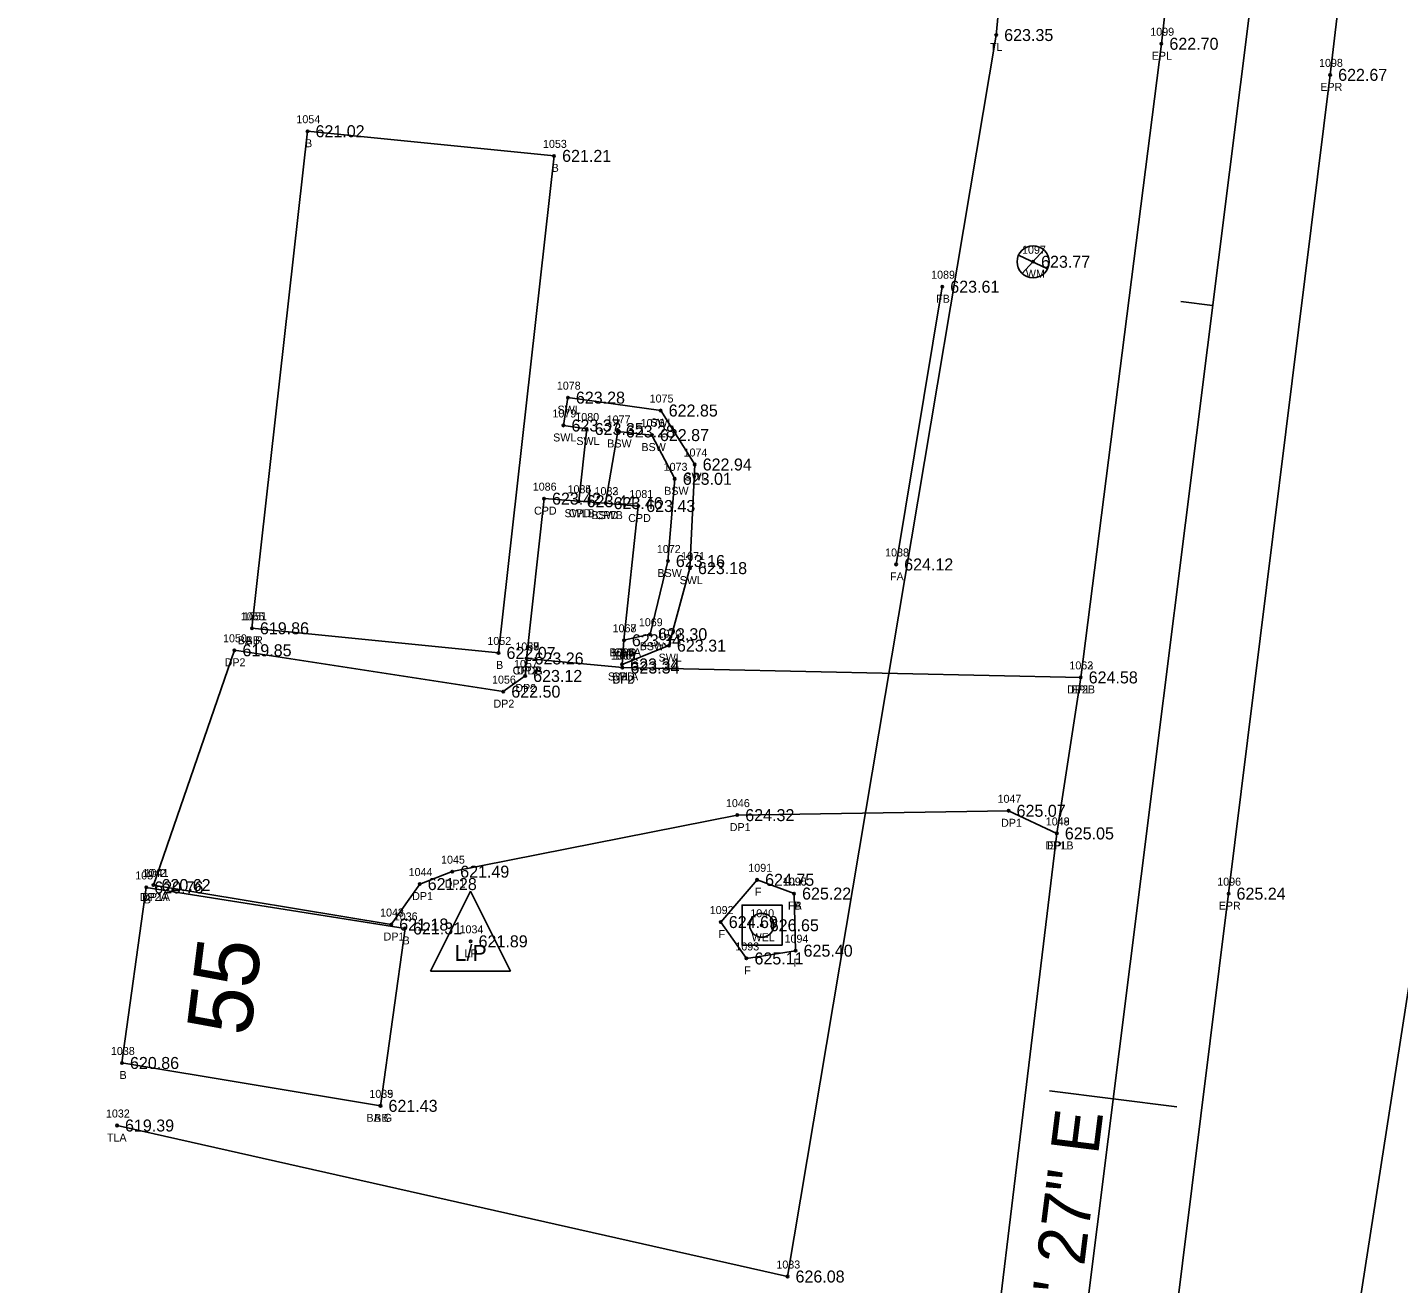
# Model space of a CAD drawing. Extents: x 1694813 to 1696862, y 1086485 to 1091027.
# Drawn here: x 1695755.8 to 1695927.2, y 1087718.4 to 1087875.5 of the extents above; entities that cross this region are included whole.
import ezdxf

# ---------------------------------------------------------------- set-up
doc = ezdxf.new("R2010")
doc.units = 0
for name, color, linetype in [('RD_EX_Bldg', 7, 'Continuous'), ('RD_EX_Bldg_txCode', 7, 'Continuous'), ('RD_EX_BldgApp_txCode', 7, 'Continuous'), ('RD_EX_Conc', 7, 'Continuous'), ('RD_EX_Conc_txCode', 7, 'Continuous'), ('RD_EX_Driveway', 7, 'Continuous'), ('RD_EX_Driveway_txCode', 7, 'Continuous'), ('RD_EX_Fence_Other', 7, 'Continuous'), ('RD_EX_Road', 7, 'Continuous'), ('RD_EX_Road_txCode', 7, 'Continuous'), ('RD_EX_SU_H2O', 7, 'Continuous'), ('RD_EX_TX_Bldg_ELEV', 7, 'Continuous'), ('RD_EX_TX_BldgApp_ELEV', 7, 'Continuous'), ('RD_EX_TX_Conc_ELEV', 7, 'Continuous'), ('RD_EX_TX_Driveway_ELEV', 7, 'Continuous'), ('RD_EX_TX_Road_ELEV', 7, 'Continuous'), ('RD_EX_TX_UT_ELEV', 7, 'Continuous'), ('RD_EX_TX_VEG_ELEV', 7, 'Continuous'), ('RD_EX_UT', 7, 'Continuous'), ('RD_EX_UT_txCode', 7, 'Continuous'), ('RD_EX_VEG', 7, 'Continuous'), ('RD_EX_VEG_txCode', 7, 'Continuous'), ('RD_HC_Cl', 7, 'Continuous'), ('RD_HC_Data', 7, 'Continuous'), ('RD_HC_Data_Tic', 7, 'Continuous'), ('RD_HC_TX_Sta50', 7, 'Continuous'), ('RD_SMD_Locator', 7, 'Continuous')]:
    doc.layers.add(name, color=color, linetype=linetype)

msp = doc.modelspace()

# ---------------------------------------------------------------- linework, layer by layer
at = {"layer": 'RD_EX_Bldg'}
for points in [[(1695783.9, 1087800.34), (1695814.72, 1087797.26), (1695821.67, 1087859.41), (1695790.85, 1087862.49), (1695783.9, 1087800.34)], [(1695799.97, 1087740.63), (1695803.04, 1087762.81), (1695770.7, 1087767.94), (1695767.66, 1087745.99), (1695799.97, 1087740.63)]]:
    msp.add_lwpolyline(points, dxfattribs=at)
at = {"layer": 'RD_EX_BldgApp_txCode'}
msp.add_circle((1695847.62, 1087763.21), 0.15, dxfattribs=at)
at = {"layer": 'RD_EX_Conc'}
for points in [[(1695830.17, 1087795.82), (1695836.02, 1087798.17), (1695838.65, 1087807.86), (1695839.24, 1087820.82), (1695834.99, 1087827.57), (1695823.39, 1087829.18), (1695822.84, 1087825.7), (1695825.74, 1087825.26), (1695824.74, 1087816.23)], [(1695830.39, 1087798.84), (1695833.67, 1087799.6), (1695835.89, 1087808.75), (1695836.75, 1087819.03), (1695833.89, 1087824.5), (1695829.63, 1087824.95), (1695828.1, 1087815.99)], [(1695818.22, 1087796.57), (1695830.21, 1087795.43), (1695830.17, 1087795.82), (1695830.17, 1087795.82), (1695830.39, 1087798.84), (1695832.18, 1087815.63), (1695828.1, 1087815.99), (1695824.74, 1087816.23), (1695820.41, 1087816.55), (1695818.22, 1087796.57)]]:
    msp.add_lwpolyline(points, dxfattribs=at)
at = {"layer": 'RD_EX_Driveway'}
for points in [[(1695771.6, 1087768.24), (1695781.72, 1087797.59), (1695815.32, 1087792.42), (1695818.05, 1087794.38), (1695818.22, 1087796.57), (1695830.21, 1087795.43), (1695887.48, 1087794.2)], [(1695771.6, 1087768.24), (1695801.31, 1087763.3), (1695804.87, 1087768.36), (1695808.93, 1087769.91), (1695844.56, 1087776.98), (1695878.47, 1087777.52), (1695884.5, 1087774.69)]]:
    msp.add_lwpolyline(points, dxfattribs=at)
at = {"layer": 'RD_EX_Fence_Other'}
msp.add_lwpolyline([(1695896.34, 1087555.36), (1695913.97, 1087661.92), (1695929.73, 1087763.6), (1695939.84, 1087832.07), (1696009.84, 1087821.33)], dxfattribs=at)
at = {"layer": 'RD_EX_Road'}
for points in [[(1695879.87, 1087561.29), (1695893.33, 1087665.71), (1695905.96, 1087767.16), (1695918.66, 1087869.54), (1695930.87, 1087972.82), (1695936.26, 1088023.68), (1695942.14, 1088076.32), (1695948.07, 1088128.17), (1695955.04, 1088181.4), (1695962.88, 1088230.72), (1695971.68, 1088284.64), (1695982.02, 1088336.12), (1695993.28, 1088388.48), (1696018.75, 1088494.48), (1696045.23, 1088599.95), (1696055.72, 1088654.41), (1696060.15, 1088705.35), (1696055.83, 1088758.02), (1696044.01, 1088812.16), (1696026.4, 1088860.33), (1696000.41, 1088911.48), (1695972.46, 1088953.82), (1695939.48, 1088998.73), (1695931.21, 1088992.88)], [(1695858.19, 1087564.9), (1695871.71, 1087668.82), (1695884.5, 1087774.69), (1695887.48, 1087794.2), (1695897.57, 1087873.43), (1695908.92, 1087975.76), (1695914.49, 1088029.24), (1695917.65, 1088054.8), (1695920.27, 1088079.09), (1695926.98, 1088130.26), (1695934.75, 1088185.09), (1695942.15, 1088234.62), (1695951.36, 1088288.06), (1695961.48, 1088338.41), (1695972.86, 1088394.13), (1695998.53, 1088499.67), (1696024.81, 1088603.86), (1696034.83, 1088656.78)]]:
    msp.add_lwpolyline(points, dxfattribs=at)
at = {"layer": 'RD_EX_SU_H2O'}
msp.add_lwpolyline([(1695845.16, 1087760.74), (1695845.16, 1087765.74), (1695850.16, 1087765.74), (1695850.16, 1087760.74)], close=True, dxfattribs=at)
msp.add_circle((1695847.62, 1087763.21), 1.5, dxfattribs=at)
at = {"layer": 'RD_EX_UT'}
for p, q in [((1695880.18, 1087844.71), (1695882.85, 1087847.6)), ((1695879.7, 1087847), (1695883.33, 1087845.29)), ((1695806.23, 1087757.47), (1695811.23, 1087767.47)), ((1695811.23, 1087767.47), (1695816.23, 1087757.47)), ((1695806.23, 1087757.47), (1695816.23, 1087757.47))]:
    msp.add_line(p, q, dxfattribs=at)
msp.add_circle((1695881.53, 1087846.17), 2, dxfattribs=at)
at = {"layer": 'RD_EX_VEG'}
msp.add_line((1695864.42, 1087808.32), (1695870.18, 1087843.05), dxfattribs=at)
for points in [[(1695767.04, 1087738.17), (1695850.84, 1087719.29), (1695876.92, 1087874.52), (1695886.77, 1087978.73), (1695882.04, 1088123.19), (1695966.35, 1088397.22), (1695987.61, 1088500.99), (1696016.82, 1088604.01), (1696023.94, 1088658.84), (1696026.75, 1088706.17), (1696020.44, 1088756.26), (1696012.04, 1088803.02), (1695995.69, 1088847.32), (1695967.16, 1088892.48), (1695790.95, 1089107.47), (1695767.01, 1089177.35), (1695741.24, 1089223.37), (1695720.39, 1089271.33), (1695703.52, 1089329.03), (1695695, 1089381.13)], [(1695851.66, 1087767.17), (1695847.04, 1087768.89), (1695842.5, 1087763.61), (1695845.71, 1087759.06), (1695851.85, 1087760.03), (1695851.66, 1087767.17)]]:
    msp.add_lwpolyline(points, dxfattribs=at)
at = {"layer": 'RD_HC_Cl'}
msp.add_line((1695866.12, 1087538.58), (1695910.69, 1087894.29), dxfattribs=at)
at = {"layer": 'RD_HC_Data_Tic'}
for p, q in [((1695903.97, 1087840.72), (1695900, 1087841.21)), ((1695891.54, 1087741.49), (1695883.6, 1087742.49)), ((1695891.54, 1087741.49), (1695899.48, 1087740.5))]:
    msp.add_line(p, q, dxfattribs=at)
at = {"layer": 'RD_SMD_Locator'}
for centre in [(1695876.92, 1087874.52), (1695897.57, 1087873.43), (1695918.66, 1087869.54), (1695790.85, 1087862.49), (1695821.67, 1087859.41), (1695881.53, 1087846.17), (1695870.18, 1087843.05), (1695823.39, 1087829.18), (1695834.99, 1087827.57), (1695822.84, 1087825.7), (1695825.74, 1087825.26), (1695829.63, 1087824.95), (1695833.89, 1087824.5), (1695839.24, 1087820.82), (1695836.75, 1087819.03), (1695820.41, 1087816.55), (1695824.74, 1087816.23), (1695824.74, 1087816.23), (1695828.1, 1087815.99), (1695828.1, 1087815.99), (1695832.18, 1087815.63), (1695835.89, 1087808.75), (1695838.65, 1087807.86), (1695864.42, 1087808.32), (1695783.9, 1087800.34), (1695783.9, 1087800.34), (1695833.67, 1087799.6), (1695781.72, 1087797.59), (1695830.39, 1087798.84), (1695830.39, 1087798.84), (1695836.02, 1087798.17), (1695814.72, 1087797.26), (1695818.22, 1087796.57), (1695818.22, 1087796.57), (1695818.22, 1087796.57), (1695830.17, 1087795.82), (1695830.17, 1087795.82), (1695830.17, 1087795.82), (1695818.05, 1087794.38), (1695830.21, 1087795.43), (1695830.21, 1087795.43), (1695887.48, 1087794.2), (1695887.48, 1087794.2), (1695815.32, 1087792.42), (1695844.56, 1087776.98), (1695878.47, 1087777.52), (1695884.5, 1087774.69), (1695884.5, 1087774.69), (1695804.87, 1087768.36), (1695808.93, 1087769.91), (1695847.04, 1087768.89), (1695770.7, 1087767.94), (1695771.6, 1087768.24), (1695771.6, 1087768.24), (1695851.66, 1087767.17), (1695851.66, 1087767.17), (1695905.96, 1087767.16), (1695801.31, 1087763.3), (1695842.5, 1087763.61), (1695803.04, 1087762.81), (1695811.23, 1087761.2), (1695851.85, 1087760.03), (1695845.71, 1087759.06), (1695767.66, 1087745.99), (1695799.97, 1087740.63), (1695799.97, 1087740.63), (1695767.04, 1087738.17), (1695850.84, 1087719.29)]:
    msp.add_circle(centre, 0.15, dxfattribs=at)

# ---------------------------------------------------------------- texts
at = {"layer": 'RD_EX_Bldg_txCode'}
for s, p in [('1054', (1695789.46, 1087863.49)), ('B', (1695790.54, 1087860.49)), ('1053', (1695820.28, 1087860.41)), ('B', (1695821.36, 1087857.41)), ('1055', (1695782.51, 1087801.34)), ('1051', (1695782.79, 1087801.34)), ('BA R', (1695782.14, 1087798.34)), ('BB', (1695783.12, 1087798.34)), ('1052', (1695813.33, 1087798.26)), ('B', (1695814.41, 1087795.26)), ('1037', (1695769.32, 1087768.94)), ('B', (1695770.4, 1087765.94)), ('1036', (1695801.63, 1087763.81)), ('B', (1695802.73, 1087760.81)), ('1038', (1695766.28, 1087746.99)), ('B', (1695767.36, 1087743.99)), ('1035', (1695798.58, 1087741.63)), ('1039', (1695798.58, 1087741.63)), ('BA G', (1695798.21, 1087738.63)), ('BB', (1695799.19, 1087738.63))]:
    msp.add_text(s, height=1, dxfattribs=at).set_placement(p)
at = {"layer": 'RD_EX_BldgApp_txCode'}
for s, p in [('1040', (1695846.19, 1087764.21)), ('WEL', (1695846.35, 1087761.21))]:
    msp.add_text(s, height=1, dxfattribs=at).set_placement(p)
at = {"layer": 'RD_EX_Conc_txCode'}
for s, p in [('1078', (1695822.01, 1087830.18)), ('1075', (1695833.61, 1087828.57)), ('1079', (1695821.46, 1087826.7)), ('SWL', (1695822.1, 1087827.18)), ('1080', (1695824.32, 1087826.26)), ('1077', (1695828.24, 1087825.95)), ('1076', (1695832.48, 1087825.5)), ('SWL', (1695833.7, 1087825.57)), ('SWL', (1695821.55, 1087823.7)), ('SWL', (1695824.45, 1087823.26)), ('BSW', (1695828.31, 1087822.95)), ('BSW', (1695832.58, 1087822.5)), ('1074', (1695837.85, 1087821.82)), ('1073', (1695835.36, 1087820.03)), ('1086', (1695819, 1087817.55)), ('1084', (1695823.35, 1087817.23)), ('1085', (1695823.35, 1087817.23)), ('SWL', (1695837.95, 1087818.82)), ('1082', (1695826.72, 1087816.99)), ('1083', (1695826.72, 1087816.99)), ('1081', (1695831.08, 1087816.63)), ('BSW', (1695835.43, 1087817.03)), ('CPD', (1695819.16, 1087814.55)), ('SWLB', (1695822.97, 1087814.23)), ('CPD', (1695823.48, 1087814.23)), ('BSWB', (1695826.32, 1087813.99)), ('CPD', (1695826.85, 1087813.99)), ('CPD', (1695830.93, 1087813.63)), ('1072', (1695834.51, 1087809.75)), ('1071', (1695837.55, 1087808.86)), ('BSW', (1695834.58, 1087806.75)), ('SWL', (1695837.36, 1087805.86)), ('1069', (1695832.26, 1087800.6)), ('1067', (1695828.98, 1087799.84)), ('1068', (1695828.98, 1087799.84)), ('1070', (1695834.59, 1087799.17)), ('1059', (1695816.83, 1087797.57)), ('1087', (1695816.83, 1087797.57)), ('BSWA', (1695828.59, 1087796.84)), ('1066', (1695828.74, 1087796.82)), ('1064', (1695828.76, 1087796.82)), ('1065', (1695828.76, 1087796.82)), ('CPD', (1695829.14, 1087796.84)), ('BSW', (1695832.36, 1087797.6)), ('1060', (1695828.76, 1087796.43)), ('SWL', (1695834.73, 1087796.17)), ('CPDA', (1695816.48, 1087794.57)), ('CPDB', (1695816.5, 1087794.57)), ('SWLA', (1695828.39, 1087793.82)), ('CPD', (1695828.92, 1087793.82)), ('CPD', (1695828.92, 1087793.82)), ('CPD', (1695828.96, 1087793.43))]:
    msp.add_text(s, height=1, dxfattribs=at).set_placement(p)
at = {"layer": 'RD_EX_Driveway_txCode'}
for s, p in [('1050', (1695780.29, 1087798.59)), ('1058', (1695816.83, 1087797.57)), ('DP2', (1695780.49, 1087795.59)), ('1057', (1695816.66, 1087795.38)), ('1061', (1695829.09, 1087796.43)), ('1062', (1695886.07, 1087795.2)), ('1056', (1695813.91, 1087793.42)), ('DP2', (1695816.99, 1087794.57)), ('DP2', (1695828.98, 1087793.43)), ('DP2', (1695816.82, 1087792.38)), ('DP2B', (1695885.78, 1087792.2)), ('DP2', (1695814.09, 1087790.42)), ('1046', (1695843.15, 1087777.98)), ('1047', (1695877.09, 1087778.52)), ('DP1', (1695843.62, 1087774.98)), ('DP1', (1695877.53, 1087775.52)), ('1048', (1695883.12, 1087775.69)), ('DP1B', (1695883.09, 1087772.69)), ('1045', (1695807.54, 1087770.91)), ('1042', (1695770.21, 1087769.24)), ('1041', (1695770.5, 1087769.24)), ('1044', (1695803.49, 1087769.36)), ('DP1', (1695807.99, 1087767.91)), ('DP2A', (1695769.88, 1087766.24)), ('DP1A', (1695770.17, 1087766.24)), ('DP1', (1695803.93, 1087766.36)), ('1043', (1695799.92, 1087764.3)), ('DP1', (1695800.36, 1087761.3))]:
    msp.add_text(s, height=1, dxfattribs=at).set_placement(p)
at = {"layer": 'RD_EX_Road_txCode'}
for s, p in [('1099', (1695896.18, 1087874.43)), ('EPL', (1695896.36, 1087871.43)), ('1098', (1695917.27, 1087870.54)), ('EPR', (1695917.43, 1087867.54)), ('1063', (1695886.07, 1087795.2)), ('EPL', (1695886.28, 1087792.2)), ('1049', (1695883.12, 1087775.69)), ('EPL', (1695883.3, 1087772.69)), ('1096', (1695904.55, 1087768.16)), ('EPR', (1695904.73, 1087765.16))]:
    msp.add_text(s, height=1, dxfattribs=at).set_placement(p)
at = {"layer": 'RD_EX_TX_Bldg_ELEV'}
for s, p in [('621.02', (1695791.85, 1087861.74)), ('621.21', (1695822.67, 1087858.66)), ('619.86', (1695784.9, 1087799.59)), ('619.86', (1695784.9, 1087799.59)), ('622.07', (1695815.72, 1087796.51)), ('620.76', (1695771.7, 1087767.19)), ('621.31', (1695804.04, 1087762.06)), ('620.86', (1695768.66, 1087745.24)), ('621.43', (1695800.97, 1087739.88)), ('621.43', (1695800.97, 1087739.88))]:
    msp.add_text(s, height=1.5, dxfattribs=at).set_placement(p)
at = {"layer": 'RD_EX_TX_BldgApp_ELEV'}
msp.add_text('626.65', height=1.5, dxfattribs=at).set_placement((1695848.62, 1087762.46))
at = {"layer": 'RD_EX_TX_Conc_ELEV'}
for s, p in [('623.28', (1695824.39, 1087828.43)), ('622.85', (1695835.99, 1087826.82)), ('623.37', (1695823.84, 1087824.95)), ('623.35', (1695826.74, 1087824.51)), ('623.28', (1695830.63, 1087824.2)), ('622.87', (1695834.89, 1087823.75)), ('622.94', (1695840.24, 1087820.07)), ('623.01', (1695837.75, 1087818.28)), ('623.42', (1695821.41, 1087815.8)), ('623.44', (1695825.74, 1087815.48)), ('623.44', (1695825.74, 1087815.48)), ('623.46', (1695829.1, 1087815.24)), ('623.46', (1695829.1, 1087815.24)), ('623.43', (1695833.18, 1087814.88)), ('623.16', (1695836.89, 1087808)), ('623.18', (1695839.65, 1087807.11)), ('623.34', (1695831.39, 1087798.09)), ('623.34', (1695831.39, 1087798.09)), ('623.30', (1695834.67, 1087798.85)), ('623.31', (1695837.02, 1087797.42)), ('623.26', (1695819.22, 1087795.82)), ('623.26', (1695819.22, 1087795.82)), ('623.34', (1695831.17, 1087795.07)), ('623.34', (1695831.17, 1087795.07)), ('623.34', (1695831.17, 1087795.07)), ('623.34', (1695831.21, 1087794.68))]:
    msp.add_text(s, height=1.5, dxfattribs=at).set_placement(p)
at = {"layer": 'RD_EX_TX_Driveway_ELEV'}
for s, p in [('619.85', (1695782.72, 1087796.84)), ('623.26', (1695819.22, 1087795.82)), ('623.34', (1695831.21, 1087794.68)), ('623.12', (1695819.05, 1087793.63)), ('624.58', (1695888.48, 1087793.45)), ('622.50', (1695816.32, 1087791.67)), ('624.32', (1695845.56, 1087776.23)), ('625.07', (1695879.47, 1087776.77)), ('625.05', (1695885.5, 1087773.94)), ('621.49', (1695809.93, 1087769.16)), ('620.62', (1695772.6, 1087767.49)), ('620.62', (1695772.6, 1087767.49)), ('621.28', (1695805.87, 1087767.61)), ('621.18', (1695802.31, 1087762.55))]:
    msp.add_text(s, height=1.5, dxfattribs=at).set_placement(p)
at = {"layer": 'RD_EX_TX_Road_ELEV'}
for s, p in [('622.70', (1695898.57, 1087872.68)), ('622.67', (1695919.66, 1087868.79)), ('624.58', (1695888.48, 1087793.45)), ('625.05', (1695885.5, 1087773.94)), ('625.24', (1695906.96, 1087766.41))]:
    msp.add_text(s, height=1.5, dxfattribs=at).set_placement(p)
at = {"layer": 'RD_EX_TX_UT_ELEV'}
for s, p in [('623.77', (1695882.53, 1087845.42)), ('621.89', (1695812.23, 1087760.45))]:
    msp.add_text(s, height=1.5, dxfattribs=at).set_placement(p)
at = {"layer": 'RD_EX_TX_VEG_ELEV'}
for s, p in [('623.35', (1695877.92, 1087873.77)), ('623.61', (1695871.18, 1087842.3)), ('624.12', (1695865.42, 1087807.57)), ('624.75', (1695848.04, 1087768.14)), ('625.22', (1695852.66, 1087766.42)), ('625.22', (1695852.66, 1087766.42)), ('624.69', (1695843.5, 1087762.86)), ('625.40', (1695852.85, 1087759.28)), ('625.11', (1695846.71, 1087758.31)), ('619.39', (1695768.04, 1087737.42)), ('626.08', (1695851.84, 1087718.54))]:
    msp.add_text(s, height=1.5, dxfattribs=at).set_placement(p)
at = {"layer": 'RD_EX_UT'}
msp.add_text('L/P', height=2, dxfattribs=at).set_placement((1695809.23, 1087758.76))
at = {"layer": 'RD_EX_UT_txCode'}
for s, p in [('1097', (1695880.15, 1087847.17)), ('WM', (1695880.63, 1087844.17)), ('1034', (1695809.85, 1087762.2)), ('LP', (1695810.48, 1087759.2))]:
    msp.add_text(s, height=1, dxfattribs=at).set_placement(p)
at = {"layer": 'RD_EX_VEG_txCode'}
for s, p in [('TL', (1695876.15, 1087872.52)), ('1089', (1695868.79, 1087844.05)), ('FB', (1695869.42, 1087841.05)), ('1088', (1695863.04, 1087809.32)), ('FA', (1695863.65, 1087806.32)), ('1091', (1695845.94, 1087769.89)), ('1090', (1695850.24, 1087768.17)), ('1095', (1695850.28, 1087768.17)), ('F', (1695846.76, 1087766.89)), ('1092', (1695841.12, 1087764.61)), ('FA', (1695850.89, 1087765.17)), ('FB', (1695850.91, 1087765.17)), ('F', (1695842.22, 1087761.61)), ('1094', (1695850.47, 1087761.03)), ('1093', (1695844.32, 1087760.06)), ('F', (1695851.57, 1087758.03)), ('F', (1695845.43, 1087757.06)), ('1032', (1695765.66, 1087739.17)), ('TLA', (1695765.78, 1087736.17)), ('1033', (1695849.45, 1087720.29))]:
    msp.add_text(s, height=1, dxfattribs=at).set_placement(p)
at = {"layer": 'RD_HC_Data'}
msp.add_text('N 7%%d 08\' 27" E', height=6, rotation=82.8592, dxfattribs=at).set_placement((1695884.1, 1087690.14))
at = {"layer": 'RD_HC_TX_Sta50'}
msp.add_text('55', height=8, rotation=82.8592, dxfattribs=at).set_placement((1695783.66, 1087749.2))

doc.saveas('drawing.dxf')
